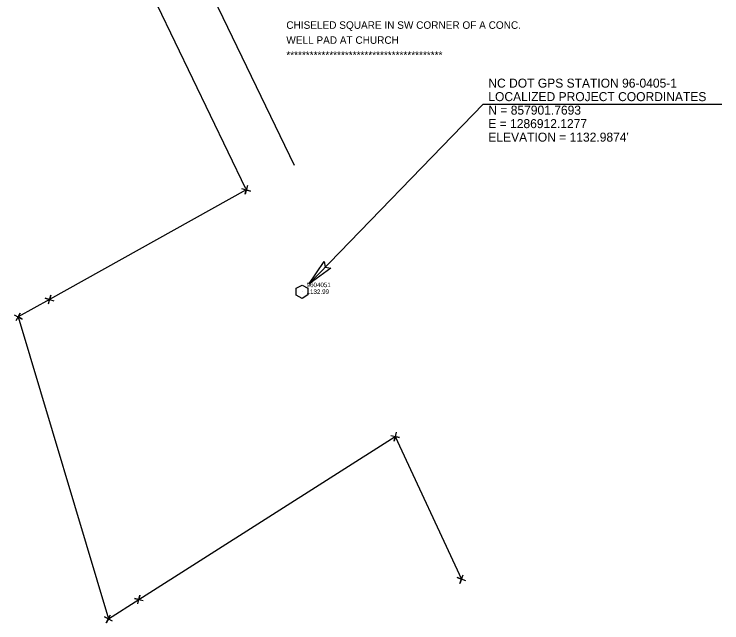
# Model space of a CAD drawing. Extents: x 1286007 to 1287145, y 857718 to 858514.
# Drawn here: x 1286752.2 to 1287145.3, y 857717.9 to 858055.9 of the extents above; entities that cross this region are included whole.
import ezdxf

# ---------------------------------------------------------------- set-up
doc = ezdxf.new("R2010")
doc.units = 0
for name, color, linetype in [('CTL GPS Vertical CELL', 7, 'Continuous'), ('CTL GPS Vertical Cogo Elevation', 7, 'Continuous'), ('CTL GPS Vertical Cogo Number', 7, 'Continuous'), ('CTL GPS Vertical Text', 7, 'Continuous'), ('CTL Sheet Text', 7, 'Continuous'), ('Default', 7, 'Continuous'), ('Exist Property Corner CELL', 7, 'Continuous'), ('Exist Property Line', 7, 'Continuous'), ('Exist Right of Way Line', 7, 'Continuous'), ('Old_Level_11', 7, 'Continuous')]:
    doc.layers.add(name, color=color, linetype=linetype)

msp = doc.modelspace()

# ---------------------------------------------------------------- linework, layer by layer
at = {"layer": 'CTL GPS Vertical CELL'}
msp.add_line((1286912.13, 857901.77), (1286912.13, 857901.77), dxfattribs=at)
msp.add_lwpolyline([(1286908.9, 857903.64), (1286912.15, 857905.45), (1286915.4, 857903.67), (1286915.35, 857899.94), (1286912.1, 857898.05), (1286908.9, 857899.87)], close=True, dxfattribs=at)
at = {"layer": 'Default'}
msp.add_line((1287012.68, 858005.86), (1287145.28, 858005.86), dxfattribs=at)
msp.add_lwpolyline([(1286915.93, 857905.99), (1287012.68, 858005.86)], dxfattribs=at)
at = {"layer": 'Exist Property Corner CELL'}
for p, q in [((1286881.13, 857958.26), (1286881.13, 857958.26)), ((1286771.87, 857897.44), (1286771.87, 857897.44)), ((1286754.4, 857887.71), (1286754.4, 857887.71)), ((1286963.79, 857821.25), (1286963.79, 857821.25)), ((1287000.67, 857742.14), (1287000.67, 857742.14)), ((1286821.45, 857730.79), (1286821.45, 857730.79)), ((1286804.57, 857720.06), (1286804.57, 857720.06))]:
    msp.add_line(p, q, dxfattribs=at)
for points in [[(1286881.82, 857960.67), (1286880.45, 857955.86), (1286881.13, 857958.26), (1286883.54, 857957.58), (1286878.73, 857958.95)], [(1286771.19, 857895.04), (1286772.56, 857899.85), (1286771.87, 857897.44), (1286769.47, 857898.13), (1286774.28, 857896.76)], [(1286752.2, 857888.9), (1286756.6, 857886.53), (1286754.4, 857887.71), (1286755.58, 857889.92), (1286753.21, 857885.51)], [(1286964.34, 857823.69), (1286963.25, 857818.81), (1286963.79, 857821.25), (1286966.23, 857820.7), (1286961.35, 857821.79)], [(1287003.02, 857741.28), (1286998.32, 857743), (1287000.67, 857742.14), (1286999.82, 857739.79), (1287001.53, 857744.49)], [(1286820.91, 857728.35), (1286822, 857733.23), (1286821.45, 857730.79), (1286819.01, 857731.33), (1286823.89, 857730.25)], [(1286806.77, 857718.88), (1286802.37, 857721.25), (1286804.57, 857720.06), (1286803.39, 857717.86), (1286805.76, 857722.26)]]:
    msp.add_lwpolyline(points, dxfattribs=at)
at = {"layer": 'Exist Property Line'}
for p, q in [((1286881.13, 857958.26), (1286771.87, 857897.44)), ((1286771.87, 857897.44), (1286754.4, 857887.71)), ((1286754.4, 857887.71), (1286804.57, 857720.06)), ((1286821.45, 857730.79), (1286963.79, 857821.25)), ((1286963.79, 857821.25), (1287000.67, 857742.14)), ((1286804.57, 857720.06), (1286821.45, 857730.79))]:
    msp.add_line(p, q, dxfattribs=at)
at = {"layer": 'Exist Right of Way Line'}
for p, q in [((1286858.72, 858073.71), (1286907.81, 857972.01)), ((1286831.62, 858060.85), (1286880.71, 857959.15))]:
    msp.add_line(p, q, dxfattribs=at)
at = {"layer": 'Old_Level_11'}
msp.add_lwpolyline([(1286928.01, 857914.83), (1286915.93, 857905.99), (1286924.35, 857918.47), (1286924.93, 857915.29)], close=True, dxfattribs=at)

# ---------------------------------------------------------------- texts
at = {"layer": 'CTL GPS Vertical Cogo Elevation'}
msp.add_text('1132.99', height=2.5, dxfattribs=at).set_placement((1286914.63, 857900.52))
at = {"layer": 'CTL GPS Vertical Cogo Number'}
msp.add_text('9604051', height=2.5, dxfattribs=at).set_placement((1286914.63, 857904.27))
at = {"layer": 'CTL GPS Vertical Text'}
for s, p in [('NC DOT GPS STATION 96-0405-1', (1287015.58, 858015.08)), ('LOCALIZED PROJECT COORDINATES', (1287015.58, 858007.58)), ('N = 857901.7693', (1287015.57, 858000.08)), ('E = 1286912.1277', (1287015.57, 857992.58)), ("ELEVATION = 1132.9874'", (1287015.57, 857985.08))]:
    msp.add_text(s, height=5, rotation=359.9944, dxfattribs=at).set_placement(p)
at = {"layer": 'CTL Sheet Text'}
for s, p in [('CHISELED SQUARE IN SW CORNER OF A CONC.', (1286903.37, 858047.73)), ('WELL PAD AT CHURCH', (1286903.37, 858039.4)), ('****************************************', (1286903.37, 858031.07))]:
    msp.add_text(s, height=4.1667, dxfattribs=at).set_placement(p)

doc.saveas('drawing.dxf')
